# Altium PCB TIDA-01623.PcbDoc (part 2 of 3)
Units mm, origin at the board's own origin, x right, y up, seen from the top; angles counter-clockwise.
Board outline 77.73 x 42 mm, 4 copper layers (Top Layer, Signal Layer 1, Signal Layer 2, Bottom Layer), stack 0.651 mm thick; 213 components, 127 nets, 575 pads, 342 vias.
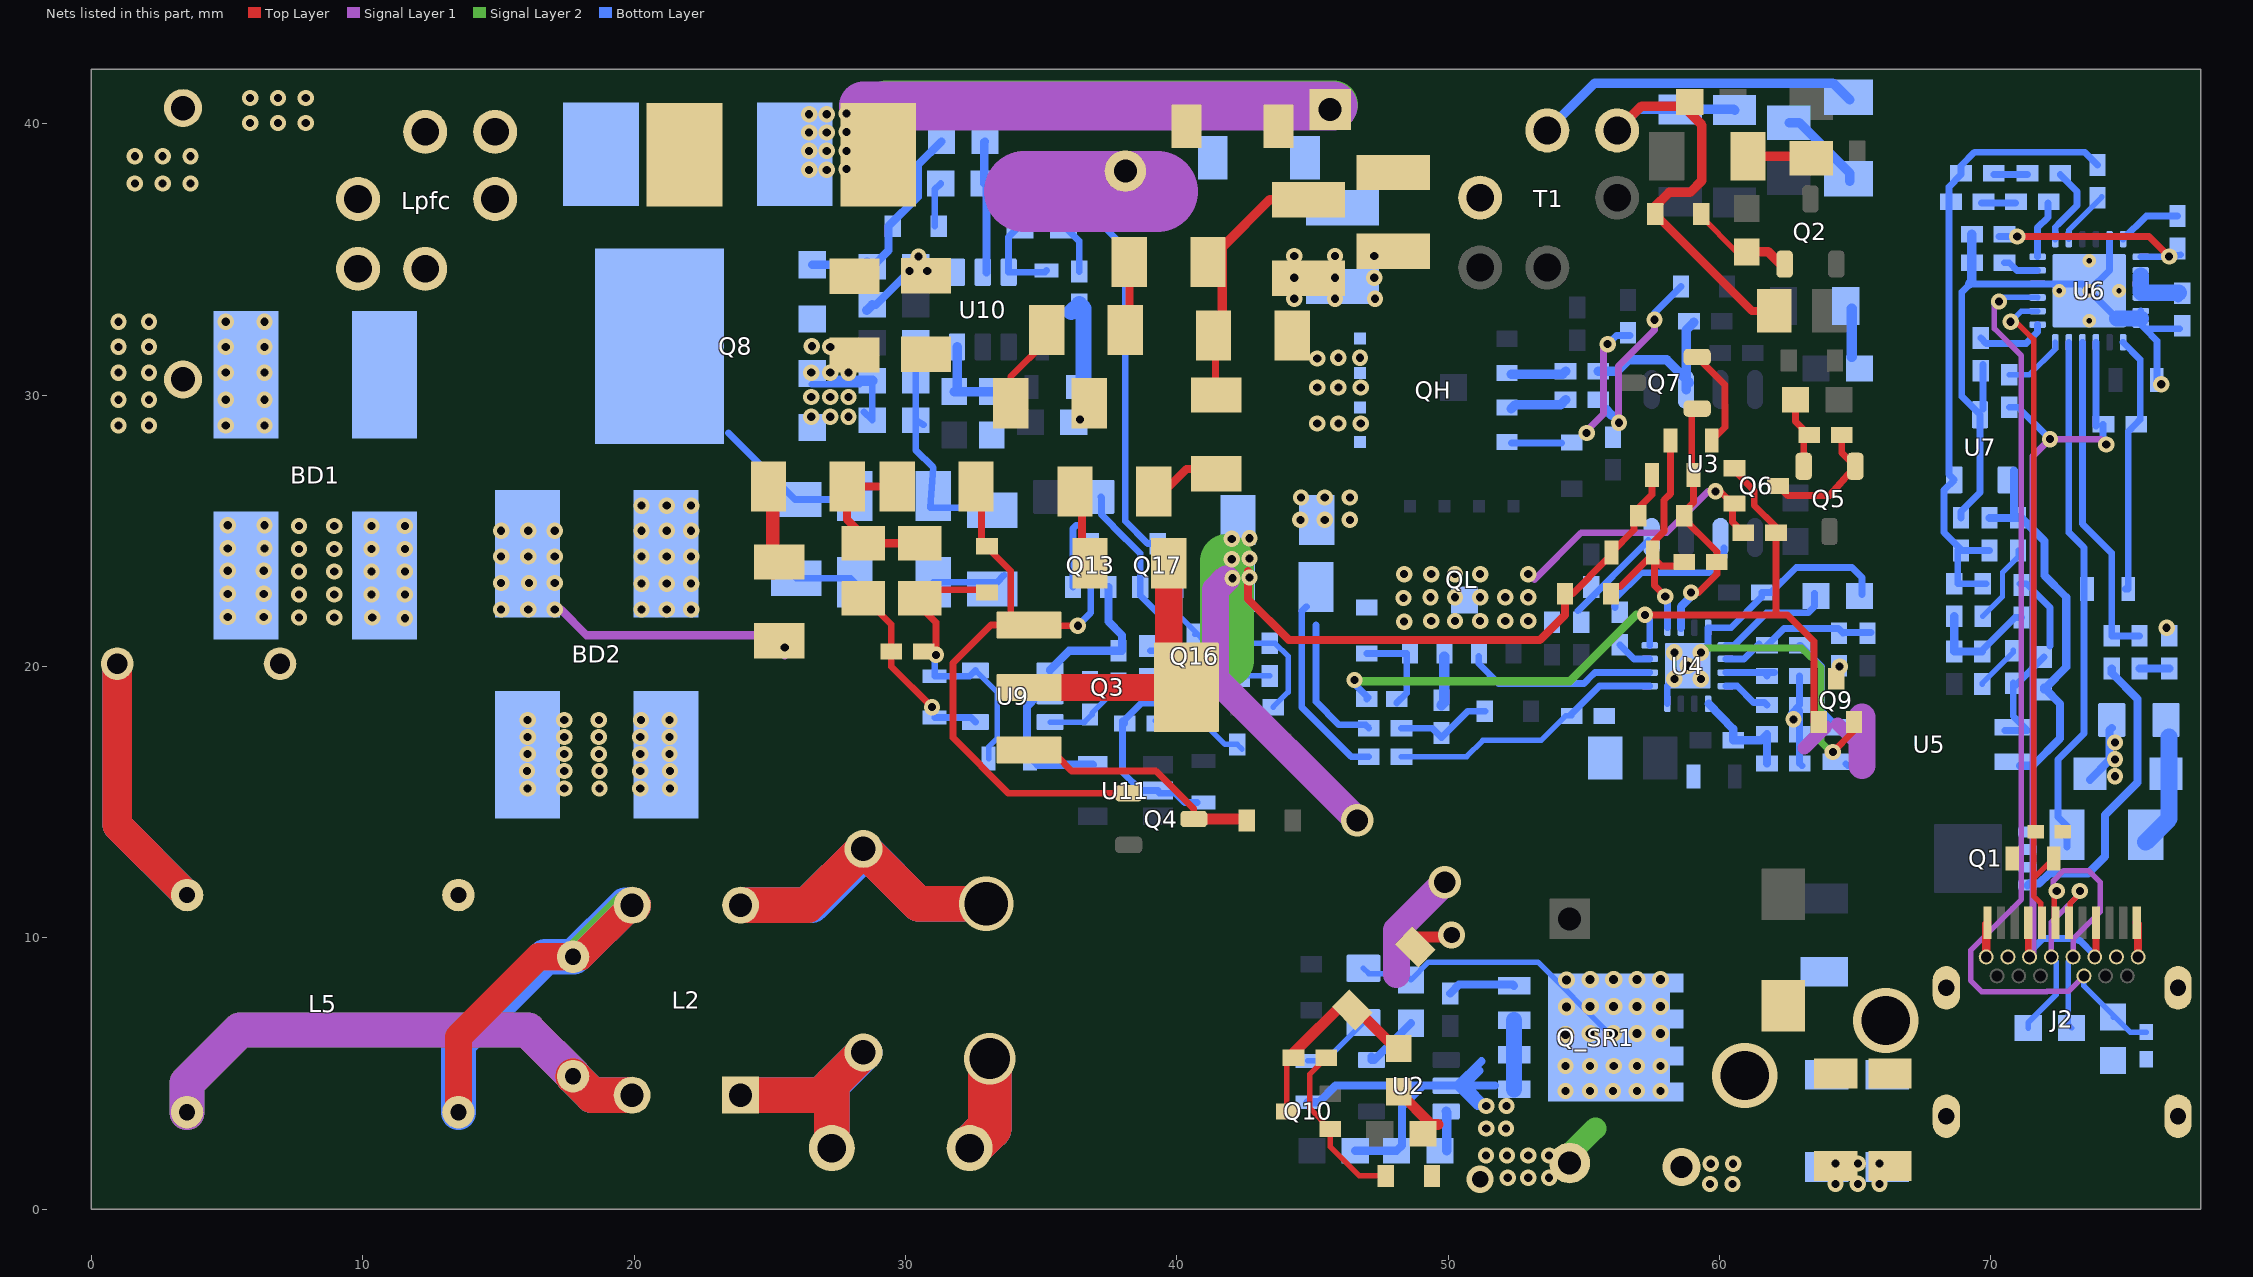
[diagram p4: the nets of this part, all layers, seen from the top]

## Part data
BD1 BD2: "Diode, P-N-Bridge, 600 V, 4 A, Z4-D"
C1: "CAP, CERM, 220 pF, 250 V, +/- 10%, X7R, 0603"
C2: "CAP, CERM, 0.33 µF, 10 V, +/- 10%, X5R, 0402"
C3: "CAP, Aluminum Polymer, 680 µF, 20 V, +/- 20%, 0.012 ohm, TH"
C4 C5 C6 C7: "CAP, CERM, 33 µF, 25 V, +/- 20%, X5R, 1206"
C8 C35: "CAP, CERM, 0.01 µF, 50 V, +/- 5%, X7R, 0402"
C10: "CAP, CERM, 6.8 µF, 25 V, +/- 10%, X5R, 0805"
C11 C12 C13: library part GRM31CR72E104KW03L, "CAP, CERM, 0.1 µF, 450 V, +/- 10%, X7T, 1206"
C14 C17 C19 C25 C52: "CAP, CERM, 0.022 µF, 50 V, +/- 10%, X7R, 0402"
C15 C20: "CAP, CERM, 0.1 µF, 50 V, +/- 10%, X7R, 0402"
C16 C51: "CAP, CERM, 0.01 µF, 50 V, +/- 10%, C0G/NP0, 0402"
C18: "CAP, CERM, 0.22 µF, 25 V, +/- 20%, X5R, 0402"
C21 C37: "CAP, CERM, 0.1 µF, 50 V, +/- 10%, X7R, 0603"
C22: "CAP, CERM, 22 µF, 35 V, +/- 20%, JB, 0805"
C23 C28: library part GRM31CR71H475KA12L, "CAP, CERM, 4.7 µF, 50 V, +/- 10%, X7R, 1206"
C26: "CAP, CERM, 22 pF, 50 V, +/- 5%, C0G/NP0, 0402"
C27 C70: "CAP, CERM, 2.2 µF, 50 V, +/- 10%, X5R, 0603"
C29 C31 C41 C61 C76 C78: "CAP, CERM, 1 µF, 50 V, +/- 10%, X7R, 0603"
C30: "CAP, CERM, 4700 pF, 50 V, +/- 10%, X7R, 0402"
C32 C33: "CAP, CERM, 560 pF, 50 V, +/- 10%, X7R, 0603"
C34: "CAP, CERM, 100 pF, 50 V, +/- 5%, C0G/NP0, 0402"
C36: "CAP, CERM, 3.3 pF, 50 V, +/- 5%, C0G/NP0, 0402"
C38: "CAP, CERM, 22 pF, 50 V, +/- 5%, C0G/NP0, 0603"
C39 C63: "CAP, CERM, 2200 pF, 50 V, +/- 5%, C0G/NP0, 0603"
C42 C43 C44: library part C3225X7R2A334K200AA, "CAP, CERM, 0.33 µF, 250 V, +/- 10%, X7T, 1210"
C47 C54: "CAP, CERM, 220 pF, 50 V, +/- 5%, C0G/NP0, 0402"
C50: "CAP, CERM, 4.7 µF, 50 V, +/- 10%, X6S, 0805"
C57: "CAP, CERM, 3900 pF, 100 V,+/- 10%, X7R, 0603"
C59: "CAP, CERM, 0.033 µF, 50 V, +/- 10%, X7R, 0603"
C60: "CAP, CERM, 1 µF, 25 V, +/- 10%, X7R, 0603"
C62 C77: "CAP, CERM, 220 pF, 50 V, +/- 5%, C0G/NP0, 0603"
C65: "CAP, CERM, 10 pF, 1000 V, +/- 5%, C0G/NP0, 1206"
C66: "CAP, CERM, 1 µF, 25 V, +/- 10%, X7R, 0805"
C75: "CAP, CERM, 0.1 µF, 250 V, +/- 10%, X7T, 0805"
C79: "CAP, CERM, 0.033 µF, 25 V, +/- 10%, X7R, 0402"
C#1: "CAP, Film, 0.47 µF, 450 V, +/- 10%, TH"
Cblk: library part 450BXW68MEFC12.5X45, "CAP, AL, 68 µF, 420 V, +/- 20%, TH"
CX1: library part 890324022017, "WCAP-FTX2 Film Capacitors, 10x6x12mm, 275V AC, 68 nF"
CX2: library part 890324024002, "WCAP-FTX2 Film Capacitors, 15x7x12.5mm, 275V AC, 220 nF"
D1: "Diode, Switching, 800 V, 3 A, SMC"
D2: "Diode, Ultrafast, 600 V, 3 A, SMC"
D3: library part PMEG10010ELRX, "Diode, Schottky, 40 V, 3 A, AEC-Q101, SOD-123W"
D4 D10: library part CZRU52C5V6, "Diode, Zener, 6.2 V, 150 mW, SOD-523F"
D6 D15: library part CZRU52C5V6, "Diode, Zener, 16 V, 150 mW, SOD-523F"
D7: "Diode, Superfast Rectifier, 600 V, 0.2A"
D8 D9: library part CZRU52C5V6, "Diode, Zener, 2 V, 150 mW, SOD-523F"
D11: "Diode, Schottky, 40 V, 0.03 A, SOD-523"
D13: library part CZRU52C5V6, "Diode, Zener, 10V, 150 mW, SOD-523F"
D14 D19 DA3: "Diode, Schottky, 50 V, 0.2 A, SOD-523F"
D16: library part CDBU0245, "Diode, Schottky, 50 V, 0.2 A, SOD-523F"
D17: "Diode, Ultrafast, 200 V, 1 A, SOD-123"
D25: library part CZRU52C5V6, "Diode, Zener, 11 V, 150 mW, SOD-523F"
D30: "Diode, Schottky, 30 V, 0.2 A, SOD-523"
DA1 DA2: "Diode, Superfast Rectifier, 600 V, 1 A, 3.5x1.6mm"
DE1 DE2: library part TPD1E0B04DPYR, "1-Channel ESD Protection Diode for USB Type-C and Antenna Protection, DPY0002A (X1SON-2)"
Dhvg1: library part CZRU52C5V6, "Diode, Zener, 24 V, 150 mW, SOD-523F"
Dz1: library part CZRU52C5V6, "Diode, Zener, 20 V, 150 mW, SOD-523F"
F1: library part 39213150000, "Fuse, 5 A, 250VAC/VDC, TH"
J2: "Connector, Receptacle, USB Type C, R/A"
L1: "WE-FI Leaded Toroidal Line Choke, L = 140µH"
L2 L5: library part 744823210, "Coupled inductor, 5.5mH+/-32%, 2.5 A, 0.040 ohm"
L3: library part 744316022, "FIXED IND 1UH 11.5A 4.75 MOHM"
L4: library part 744042330, "Inductor, Multilayer, Ferrite, 0.68 µH, 0.19 A, 0.67  ohm, 1206"
Logo2: library part Pb-Free
LOGO5 LOGO6 LOGO7 LOGO8: library part IEC_HighVoltage, "IEC 61010-1 High Voltage Warning"
LOGO9: library part IEC_HotSurface, "IEC 61010-1 Hot Surface Warning"
Lpfc: library part "RM4, 070-5754", "Transformer 6-Terminal , THT, Vertical, RM Style Bobbins, RM4"
Q1: library part CSD17578Q3A, "MOSFET, N-CH, 30 V, 27 A, DNH0008A (VSONP-8)"
Q2: library part PMV213SN,215, "MOSFET, N-CH, 100 V, 1.9 A, SOT-23"
Q3: library part STN3N40K3, "MOSFET, N-CH, 600 V, 0.3 A, SOT-223"
Q4: "MOSFET, N-CH, 60 V, 115 A, SOT-23"
Q5: library part DMP3099L-7, "'MOSFET P-CH 50V 0.18A SOT23"
Q6 Q9 Q13 Q16 Q17: "MOSFET, N-CH, 60 V, 0.31 A, SOT-323"
Q7: "MOSFET, N-CH, 600 V, 0.021 A, AEC-Q101, SOT-23"
Q8: library part IPL65R099C7, "CoolMos C7 700V Power Transistor"
Q10: "MOSFET, N-CH, 100 V, 0.17 A, SOT-323"
Q_SR1: "MOSFET, N-CH, 150 V, 87 A, PG-TDSON-8"
QH QL: library part CMP-0077886-1, "650V AllGaN Power IC with iDrive, PQFN-8"
R1: "RES, 0.005, 1%, 0.25 W, 1206"
R2: "RES, 22, 5%, 0.125 W, 0805"
R3: "RES, 1.00 k, 1%, 0.063 W, 0402"
R4: "RES, 2.21 M, 1%, 0.25 W, 1206"
R5 R25 R81 R87 R88: "RES, 10.0, 1%, 0.063 W, 0402"
R6 RG1: "RES, 10.0, 1%, 0.1 W, 0603"
R8 R31 R84 R95 R99: "RES, 100 k, 1%, 0.063 W, 0402"
R10 R27: "RES, 100, 1%, 0.1 W, 0603"
R11: "RES, 5.11, 1%, 0.1 W, 0603"
R12 R82: "RES, 100, 1%, 0.063 W, 0402"
R13 R19 R85 R96: "RES, 0, 5%, 0.063 W, 0402"
R14: "RES, 825, 1%, 0.063 W, 0402"
R15: "RES, 2.00 k, 1%, 0.063 W, 0402"
R16: "RES, 90.9 k, 1%, 0.063 W, 0402"
R17 R18 R75 R76: "RES, 0.22, 1%, 0.25 W, 1206"
R20: "RES, 61.9 k, 1%, 0.063 W, 0402"
R21: "RES, 75.0 k, 1%, 0.063 W, 0402"
R22 R29: "RES, 10.0 k, 1%, 0.063 W, 0402"
R23: "RES, 432 k, 1%, 0.063 W, 0402"
R24: "RES, 49.9 k, 1%, 0.063 W, 0402"
R26: library part CRCW0603150KFKEA, "RES, 150 k, 1%, 0.1 W, 0603"
R28: "RES, 562, 1%, 0.063 W, 0402"
R30 R37 R41: "RES, 150 k, 1%, 0.063 W, 0402"
R32 R86: "RES, 30.1 k, 1%, 0.063 W, 0402"
R33 Rb2: "RES, 56.2 k, 1%, 0.063 W, 0402"
R34: "RES, 15.0 k, 1%, 0.063 W, 0402"
R35: "RES, 121, 1%, 0.1 W, 0603"
R36: "RES, 1.00 M, 1%, 0.063 W, 0402"
R38: "RES, 274 k, 1%, 0.063 W, 0402"
R43: "RES, 24.9, 1%, 0.1 W, 0603"
R44 R45: "RES, 1.00, 1%, 0.125 W, 0805"
R46 R47 R48 R60 R61 R62 R71 R72 R73: "RES, 3.24 M, 1%, 0.25 W, 1206"
R49 R50 R51: "RES, 1.00 k, 1%, 0.25 W, 1206"
R63: "RES, 274 k, 1%, 0.1 W, 0603"
R65: "RES, 2.00, 1%, 0.1 W, 0603"
R66: "RES, 64.9 k, 1%, 0.1 W, 0603"
R68: "RES, 182 k, 1%, 0.063 W, 0402"
R74: "RES, 24.3 k, 0.5%, 0.1 W, 0603"
R78: "RES, 750, 1%, 0.1 W, 0603"
R80: "RES, 47.5 k, 1%, 0.063 W, 0402"
R83: "RES, 178 k, 1%, 0.063 W, 0402"
R97: "RES, 39.2 k, 1%, 0.063 W, 0402"
R98: "RES, 3.16 M, 1%, 0.125 W, 0805"
Rb1: "RES, 332 k, 1%, 0.063 W, 0402"
RG2: "RES, 1.00, 1%, 0.1 W, 0603"
RG3: "RES, 82.5 k, 1%, 0.1 W, 0603"
RT1: "Thermistor NTC, 47.0k ohm, 1%, 0603"
Rvs1: library part CRCW060375K0FKEA, "RES, 75.0 k, 1%, 0.1 W, 0603"
Rvs2: "RES, 12.4 k, 1%, 0.063 W, 0402"
T1: library part Transformer, "Transformer, 120 uH, SMT"
U2: "UCC24612-1DBV, DBV0005A (SOT-23-5)"
U3: library part ISO7310CDR, "Robust EMC, Low Power, Single Channel Digital Isolator, D0008A (SOIC-8)"
U4: "Active-Clamp Flyback Controller, RTE0016C (WQFN-16)"
U5: library part HMHA2801A, "Optocoupler, 3.75 kV, 80-160% CTR, SMT"
U6: "USB Type-C and USB PD Source Controller, RGE0024H (VQFN-24)"
U7: library part TL431ACDBZR, "Adjustable Precision Shunt Regulator, 34 ppm / degC, 100 mA, 0 to 70 degC, 3-pin SOT-23 (DBZ), Green (RoHS & no Sb/Br)"
U9: "Tiny CMOS Operational Amplifier with Rail-to-Rail Input and Output, DBV0005A"
U10: "6-Pin Single-Phase Transition-Mode PFC Controller, DBV0006A (SOT-23-6)"
U11: "Micropower 100 mA Ultra Low-Dropout Regulator, 5-pin SOT-23"

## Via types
v1: diameter 0.6, hole 0.3, Top Layer to Bottom Layer, 299 vias
v2: diameter 0.635, hole 0.33, Top Layer to Bottom Layer, 15 vias
v3: diameter 0.5, hole 0.2, Top Layer to Bottom Layer, 12 vias
v4: diameter 0.61, hole 0.305, Top Layer to Bottom Layer, 5 vias
v5: diameter 1, hole 0.6, Top Layer to Bottom Layer, 2 vias
v6: diameter 2.4, hole 1.8, Top Layer to Bottom Layer, 2 vias
v7: diameter 1.2, hole 0.8, Top Layer to Bottom Layer, 2 vias
v8: diameter 1.4, hole 0.8, Top Layer to Bottom Layer, 2 vias
v9: diameter 2, hole 1.6, Top Layer to Bottom Layer, 1 vias
v10: diameter 1.9, hole 1.5, Top Layer to Bottom Layer, 1 vias
v11: diameter 0.6/0.6/0.6/0.6 (per signal layer), hole 0.3, Top Layer to Bottom Layer, 1 vias

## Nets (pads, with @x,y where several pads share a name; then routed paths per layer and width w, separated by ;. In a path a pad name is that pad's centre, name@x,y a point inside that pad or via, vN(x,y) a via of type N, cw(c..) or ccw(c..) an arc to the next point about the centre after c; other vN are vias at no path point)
5V_LDO: C76.2 R84.2 U9.2 U11.5 | length 7.1
  Bottom Layer w0.3: R84.2@36.875,19.425 36.375,19.425 35.85,18.9 U9.2@35.325,18.9 34.85,18.9 34.475,18.525 34.475,16.775 34.875,16.375 U11.5@36.9,16.375
390V_BUS: C11.2 C12.2 C13.2 C42.2 C43.2 C44.2 Cblk.1 D1.1 D2.1 R4.2 R49.1 R60.2 T1.6 | length 43.4
  Top Layer w0.25: R49.1@41.425,30.175 41.425,32.1 R4.2@41.425,32.375
  Top Layer w0.35: R4.2@41.425,32.1 41.675,32.35 41.675,35.45 43.425,37.2 C44.2@44.85,37.2
  Signal Layer 1 w1.8: 28.45,40.65 Cblk.1@45.75,40.65
  Signal Layer 2 w1.8: 29.3,40.7 Cblk.1@45.775,40.7
  Bottom Layer w0.35: T1.6@51.101,37.201 T1.6@51.15,37.25
  other v1: 26.45,38.3 27.1,38.3 27.825,38.325 26.45,39 27.1,39 27.825,39 26.45,39.675 27.1,39.675 27.825,39.7 26.45,40.35 27.1,40.35 27.825,40.375
AC_IN: C77.1 R83.1 R98.1 U9.4 | length 6.5
  Top Layer w0.25: R98.1@28.725,22.509 28.725,22.3 29.475,21.55 R83.1@29.475,20.55 29.475,20 v1(30.975,18.5)
  Bottom Layer w0.25: C77.1@31.075,18.113 32.412,18.113 U9.4@32.575,17.95
AC_R: BD1.1 BD2.1 C#1.1 D1.2 Lpfc.4 Lpfc.5 Lpfc.6 R46.2 | length 9.2
  Signal Layer 1 w0.3: v1(17.075,22.1) 17.3,22.1 18.25,21.15 24.8,21.15 25.55,20.4
  other v1: 25.55,20.7 15.1,22.1 16.1,22.1 15.1,23.075 16.125,23.075 17.075,23.075 15.1,24.05 16.1,24.05 17.075,24.05 15.1,25 16.1,25 17.075,25 1.6,37.8 2.625,37.8 3.65,37.8 1.6,38.8 2.625,38.8 3.65,38.8 5.85,40.025 6.875,40.025 7.9,40.025 5.85,40.95 6.875,40.95 7.9,40.95
B/O: D15.1 Q3.1 Q4.1 Q13.3 R48.1 | length 23.5
  Top Layer w0.25: R48.1@32.6,26.625 32.8,26.425 32.8,24.425 32.975,24.425 33.875,23.525 33.875,21.525 33.15,21.525 31.75,20.125 31.75,17.375 33.8,15.325 Q4.1@38.225,15.325 ; Q3.1@34.55,21.525 34.575,21.5 v1(36.35,21.5)
  Bottom Layer w0.25: v1(36.35,21.5) 36.825,21.975 Q13.3@36.825,24.525
BUR: C47.1 Rb1.1 Rb2.2 U4.13 | length 4.1
  Bottom Layer w0.305: U4.13@59.6,18.625 60.5,17.7 Rb1.1@60.5,17.275 61.525,17.275 C47.1@61.75,17.5 Rb2.2@61.75,16.425
CC1: C32.1 DE1.2 J2.A5 U6.2 | length 24.9
  Top Layer w0.203: v1(70.725,32.7) 70.925,32.7 71.573,32.052 71.573,12.186 ; J2.A5@71.875,10.555 71.827,10.603 71.827,11.28 71.573,11.533 71.573,12.186 ; C32.1@72.312,12.925 71.573,12.186
  Bottom Layer w0.203: v1(70.725,32.7) 71.12,33.095 U6.2@71.72,33.095
CC2: C33.2 DE2.2 J2.B5 U6.3 | length 35.9
  Signal Layer 1 w0.203: v1@70.304,33.627 70.125,33.448 70.125,33.151 70.123,33.149 70.123,32.949 70.123,32.451 71.125,31.449 71.125,11.41 69.248,9.534 69.248,8.427 69.657,8.018 72.064,8.018 72.07,8.025 72.855,8.025 J2.B5@73.425,8.595
  Bottom Layer w0.203: v1@70.304,33.595 70.544,33.595 70.546,33.597 71.72,33.597 U6.3@71.72,33.595 ; J2.B5@73.425,8.595 73.425,8.225 75.125,6.525 DE2.2@75.725,6.525 ; C33.2@74.5,7.075 C33.2@74.55,7.075
  other v1: 70.3,33.45
COMP: C59.1 C60.1 Q17.3 U10.6 | length 19.8
  Bottom Layer w0.25: C59.1@35.2,34.587 35.138,34.525 U10.6@33.8,34.525 33.8,35.825 C60.1@34.225,36.25 34.39,36.25 35.19,37.05 36.46,37.05 38.1,35.41 38.1,25.35 38.925,24.525 Q17.3@39.3,24.525
CS: C26.2 R14.1 U4.1 | length 10.2
  Bottom Layer w0.2: R14.1@48.275,16.675 50.675,16.675 51.275,17.275 53.425,17.275 54.325,18.175 C26.2@54.55,18.175
  Bottom Layer w0.254: C26.2@54.512,18.212 55.575,19.275 U4.1@57.425,19.275
CTL: C35.2 C36.1 R13.1 R15.1 R21.2 R30.1 R41.2 U7.2 | length 23.6
  Bottom Layer w0.25: R41.2@68.775,24.275 68.775,23.05 C35.2@69.825,23.05 ; C36.1@69.95,24.275 R41.2@68.9,24.275 68.9,24.315 68.275,24.94 68.275,26.5 U7.2@68.65,26.875 68.625,26.9 68.45,27.075 68.45,37.675 68.9,38.125 68.9,38.45 69.4,38.95 73.45,38.95 R21.2@73.925,38.475
CTL1: R20.2 U6.6 | length 2.1
  Bottom Layer w0.25: U6.6@71.72,35.095 71.72,36.17 72.1,36.55 R20.2@72.1,37.075
CTL2: R16.2 U6.7 | length 3
  Bottom Layer w0.25: U6.7@72.37,35.745 72.37,36.184 72.55,36.364 72.55,36.365 73.175,36.99 73.175,37.5 R16.2@72.55,38.125
CTL3: R21.1 U6.8 | length 2.1
  Bottom Layer w0.2: U6.8@72.87,35.745 72.87,36.083 R21.1@74.087,37.3
DAUX2_2: DA2.2 T1.1 | length 12.2
  Bottom Layer w0.35: T1.1@53.625,39.725 T1.1@53.65,39.75 55.398,41.498 64.177,41.498 DA2.2@64.8,40.875
DN: J2.A7 J2.B7 R27.2 | length 7.4
  Top Layer w0.203: J2.A7@72.875,10.555 72.923,10.603 72.923,11.28 73.368,11.725 v1@73.375,11.725
  Signal Layer 1 w0.203: J2.B7@72.225,9.295 72.225,10.575 v1@73.375,11.725
  Bottom Layer w0.203: R27.2@71.375,6.675 71.375,6.875 72.4,7.9 72.4,8.178 72.402,8.18 72.402,9.118 J2.B7@72.225,9.295
  other v1: 73.275,11.725
DP: J2.A6 J2.B6 R27.1 | length 9.5
  Top Layer w0.2: v11@72.3,11.725 72.325,11.7 72.325,10.605 J2.A6@72.375,10.555
  Signal Layer 1 w0.2: v11@72.3,11.725 72.3,12.1 72.675,12.475 73.6,12.475 74.025,12.05 74.025,10.95 73.025,9.95 J2.B6@73.025,9.295
  Bottom Layer w0.2: R27.1@72.975,6.675 72.85,6.8 72.85,9.12 J2.B6@73.025,9.295
  other v11: 72.425,11.725
DRAIN: C65.1 D2.2 Lpfc.1 Lpfc.2 Lpfc.3 Q8.5 R71.2 | length 6.1
  Bottom Layer w0.25: 23.475,28.6 25.925,26.15 R71.2@25.975,26.15 28,26.15 C65.1@28.1,26.25 ; C65.1@28.1,26.5 C65.1@28.1,26.25 ; C65.1@28.125,26.275 C65.1@28.1,26.25 ; C65.1@28.25,26.375 C65.1@28.35,26.475
DRV: RG1.1 RG2.1 U10.5 | length 4.8
  Bottom Layer w0.3: RG2.1@32.9,37.8 32.9,39.325 RG1.1@32.925,39.35 ; U10.5@32.979,34.521 RG2.1@32.979,37.8
DVDD: C18.1 R19.2 U6.13 | length 8.1
  Top Layer w0.254: v1(70.97,35.845) 75.824,35.845 v1(76.567,35.102)
  Bottom Layer w0.254: C18.1@70.3,35.85 v1(70.97,35.845) ; U6.13@75.52,35.095 76.567,35.095 R19.2@76.995,35.17
F: Q_SR1.5 Q_SR1.6 Q_SR1.7 Q_SR1.8 Q_SR1.9 R2.1 R10.2 | length 10.7
  Bottom Layer w0.2: R2.1@46.875,8.875 47.075,8.675 48.4,8.675 R10.2@48.625,8.45 49.275,9.1 53.3,9.1 55.925,6.475 Q_SR1.9@55.925,6.325
  other v1: 54.325,4.35 55.225,4.35 56.075,4.35 56.95,4.35 57.825,4.35 54.325,5.275 55.225,5.275 56.1,5.275 56.95,5.275 57.825,5.275
  other v2: 54.327,6.436 55.225,6.475 56.089,6.475 56.952,6.475 57.816,6.475 54.36,7.457 55.233,7.47 56.096,7.47 56.96,7.47 57.823,7.47 54.36,8.445 55.233,8.459 56.096,8.459 56.96,8.459 57.823,8.459
  other v6: 60.925,4.925
FB: C54.2 R23.2 R32.1 U4.10 | length 5.7
  Bottom Layer w0.25: U4.10@60.225,20.275 60.9,20.275 R32.1@61.45,20.825 ; R32.1@61.7,20.725 R32.1@61.75,20.775 62.375,21.4 64.375,21.4 64.55,21.225 64.575,21.25 C54.2@65.575,21.25
GATE: D14.2 Q8.1 RG1.2 RG3.2 | length 8.1
  Bottom Layer w0.3: Q8.1@26.565,34.8 RG3.2@28.7,34.8 ; RG3.2@28.575,34.925 RG3.2@28.7,34.8 ; RG1.2@31.325,39.35 30.45,38.475 30.45,37.3 29.375,36.225 29.375,35.325 RG3.2@28.775,34.725 RG3.2@28.7,34.8
GDNG: R3.2 R5.1 U6.22 | length 12.3
  Bottom Layer w0.25: U6.22@73.37,31.945 73.37,25.255 74.45,24.175 R5.1@74.45,21.125 R3.2@75.475,21.125
GDNS: Q1.1 Q1.2 Q1.3 R1.1 R43.2 U6.23 | length 19.4
  Bottom Layer w0.25: R1.1@72.8,13.35 72.8,14.125 72.475,14.45 72.475,16.575 73.425,17.525 73.425,24.375 72.87,24.93 U6.23@72.87,31.945
HIGH_VOUT: D25.2 Q16.1 R22.1 | length 5.7
  Bottom Layer w0.2: R22.1@39.2,18 R22.1@39.275,18 ; R22.1@39.275,17.9 40.175,17.9 ; Q16.1@41.3,19.575 41.3,19.025 40.175,17.9 ; D25.2@42.4,16.95 D25.2@42.225,17.125 41.775,17.125 41,17.9 40.175,17.9
HVG: C39.2 Dhvg1.1 Q7.1 R36.2 U4.6 | length 9.7
  Top Layer w0.25: Dhvg1.1@58.55,25.55 59.037,26.037 59.037,26.262 C39.2@59.037,27.05 58.975,27.112 58.975,29.3 Q7.1@59.175,29.5 ; Dhvg1.1@58.563,25.563 59.9,24.225 R36.2@59.9,23.85 59.9,23.4 59.225,22.725 v1(58.95,22.725)
  Bottom Layer w0.305: U4.6@58.575,21.425 58.575,22.2 58.95,22.575 v1(58.95,22.725)
INH: C34.2 R88.1 U3.6 | length 6.5
  Bottom Layer w0.35: R88.1@55.525,30.875 56.225,30.875 56.65,31.3 58.05,31.3 U3.6@58.765,30.585 ; U3.6@58.765,30.2 U3.6@58.765,30.585 ; U3.6@58.89,30.46 U3.6@58.765,30.585 ; C34.2@59.05,32.675 58.765,32.39 U3.6@58.765,30.585
ISNS: C2.2 R43.1 U6.19 | length 9.6
  Bottom Layer w0.25: U6.19@74.87,31.945 75.5,31.315 75.5,29.1 75.325,28.925 75.062,28.662 R43.1@75.062,22.85 R43.1@74.95,22.85
L-LINE: F1.2 | length 14.4
  Top Layer w1.6: F1.2@32.365,2.25 33.1,2.985 v10(33.1,5.55)
  Signal Layer 1 w1.6: F1.2@32.365,2.25 33.1,2.985 v10(33.1,5.55)
  Signal Layer 2 w1.6: F1.2@32.365,2.25 33.1,2.985 v10(33.1,5.55)
  Bottom Layer w1.6: F1.2@32.365,2.25 33.1,2.985 v10(33.1,5.55)
N-LINE: CX1.1 L2.4 | length 42.9
  Top Layer w1.3: L2.4@23.925,11.2 26.375,11.2 CX1.1@28.45,13.275 30.475,11.25 v9(32.975,11.25)
  Signal Layer 1 w1.3: L2.4@23.925,11.2 26.375,11.2 CX1.1@28.45,13.275 30.475,11.25 v9(32.975,11.25)
  Signal Layer 2 w1.3: L2.4@23.925,11.2 26.375,11.2 CX1.1@28.45,13.275 30.475,11.25 v9(32.975,11.25)
  Bottom Layer w1.3: L2.4@23.975,11.2 26.55,11.2 28.537,13.187 30.475,11.25 v9(32.975,11.25)
NetBD1_2: BD1.2 BD1.3 L1.2
  other v1: 11.55,21.775 7.65,21.8 8.95,21.8 10.35,21.8 5.025,21.825 6.35,21.825 7.65,22.65 8.95,22.65 10.325,22.65 11.55,22.65 5.025,22.675 6.35,22.675 7.65,23.5 8.95,23.5 10.325,23.5 11.55,23.5 5.025,23.525 6.35,23.525 7.65,24.325 8.95,24.325 10.325,24.325 11.55,24.325 5.025,24.35 6.375,24.35 7.65,25.175 8.95,25.175 10.325,25.175 11.55,25.175 5.025,25.2 6.375,25.2
NetBD2_2: BD2.2 BD2.3 L5.3
  other v1: 16.075,15.5 17.425,15.5 18.725,15.5 20.225,15.5 21.325,15.5 16.05,16.15 17.425,16.15 18.725,16.15 20.225,16.15 21.325,16.15 16.075,16.775 17.425,16.775 18.7,16.775 20.225,16.775 21.3,16.775 16.075,17.4 17.425,17.4 18.7,17.4 20.225,17.4 21.3,17.4 16.075,18.025 17.425,18.025 18.7,18.025 20.25,18.025 21.3,18.025
NetC1_2: C1.2 R2.2 | length 2.6
  Bottom Layer w0.2: C1.2@44.825,5.462 45.462,5.462 R2.2@46.875,6.875
NetC8_1: C8.1 R3.1 | length 1.1
  Bottom Layer w0.3: R3.1@75.475,19.925 C8.1@76.575,19.925
NetC16_1: C16.1 D8.1 R81.2 | length 6.3
  Signal Layer 1 w0.254: v1(56.294,28.979) 56.275,28.998 56.275,31.074 57.6,32.399 v1(57.6,32.775)
  Bottom Layer w0.254: v1(57.6,32.775) 57.6,33.025 D8.1@58.575,34
  Bottom Layer w0.35: 55.773,29.5 56.025,29.249
NetC20_1: C20.1 U6.1 | length 2.6
  Bottom Layer w0.254: C20.1@69.625,32.1 69.825,31.9 71.3,31.9 71.72,32.32 U6.1@71.72,32.595
NetC29_2: C29.2 D17.1 Q10.3 R24.1 | length 7.2
  Top Layer w0.2: Q10.3@44.05,3.6 44.05,5.325 R24.1@44.3,5.575
  Top Layer w0.4: R24.1@44.3,5.575 44.3,5.75 46.267,7.717 47.809,6.175 C29.2@47.825,6.175
NetC30_1: C30.1 R28.1 | length 1.7
  Bottom Layer w0.2: R28.1@69.675,19.35 69.675,19.374 70.825,20.524 C30.1@70.825,20.6
NetC30_2: C30.2 R29.1 R34.2 U5.1 | length 7.2
  Bottom Layer w0.25: U5.1@70.51,17.635 71.35,17.635 70.825,18.16 C30.2@70.825,19.4 ; C30.2@70.9,19.3 R34.2@71.95,20.35 ; R29.1@71.075,23.05 71.3,23.05 72.175,22.175 R34.2@72.175,20.75
NetC35_1: C35.1 R33.2 | length 3
  Bottom Layer w0.2: C35.1@69.7,21.85 70.425,22.575 70.425,23.465 71,24.04 R33.2@71,24.275
NetC36_2: C36.2 R33.1 R34.1 U5.2 U7.1 | length 14.5
  Bottom Layer w0.3: C36.2@69.95,25.475 R33.1@71,25.475 R33.1@70.975,25.5 ; R33.1@70.85,25.5 70.85,27.225 ; R33.1@70.875,25.475 71.125,25.475 71.975,24.625 71.975,23.35 72.775,22.55 72.775,19.975 R34.1@72.025,19.225 ; U5.2@71.075,16.34 71.54,16.34 72.55,17.35 72.55,18.625 71.988,19.188 71.95,19.225 R34.1@72.025,19.225 ; R34.1@71.95,19.15 R34.1@72.025,19.225
NetC42_1: C42.1 C43.1 C44.1 QH.5 QH.6 QH.7 QH.8 R4.1
  other v1: 45.175,28.95 45.95,28.95 46.775,28.95 45.175,30.275 45.95,30.275 46.775,30.275 45.175,31.35 45.95,31.375 46.75,31.375 44.325,33.55 45.825,33.55 47.3,33.55 44.325,34.325 45.825,34.325 47.275,34.325 44.325,35.125 45.825,35.125 47.275,35.125
NetC51_1: C51.1 D9.1 R82.2 | length 3.6
  Bottom Layer w0.25: C51.1@48.275,17.725 49.4,17.725 49.75,17.375 50.725,18.35 D9.1@51.35,18.35
NetC57_1: C57.1 C65.2 R73.1 R74.2 R78.2 | length 8.7
  Bottom Layer w0.25: R78.2@30.375,31.925 C57.1@30.375,30.525 R74.2@30.375,29.075 ; R74.2@30.675,28.904 R74.2@30.375,29.075 ; R73.1@32.94,25.85 30.915,25.85 31.025,27.325 30.375,27.975 R74.2@30.375,29.075
NetC57_2: C57.2 Q8.2 Q8.3 Q8.4 R74.1 R75.2 R76.2 | length 5
  Bottom Layer w0.25: Q8.3@26.55,30.395 C57.2@28.3,30.395 ; R74.1@28.475,29.375 R74.1@28.775,29.075 C57.2@28.775,30.525
  Bottom Layer w0.4: 27.4,30.525 C57.2@28.775,30.525
  other v1: 26.525,29.2 27.225,29.2 27.9,29.2 26.525,29.925 27.225,29.925 27.9,29.925 26.525,30.825 27.225,30.825 27.9,30.825 27.225,31.775 26.55,31.8
NetC60_2: C60.2 R68.2 | length 1.9
  Bottom Layer w0.25: C60.2@35.825,36.25 36.4,35.675 R68.2@36.4,34.55
NetC75_1: C75.1 R47.1 R48.2 R98.2 | length 6.1
  Top Layer w0.3: R48.2@29.7,26.625 R47.1@27.85,26.625 27.85,25.416 28.725,24.541 30.359,24.541 C75.1@30.475,24.425
NetC79_1: C79.1 Q16.3 Q17.1 R31.2 R95.1 | length 8
  Bottom Layer w0.2: Q17.1@39.95,22.925 40.1,22.775 40.1,21.85 Q16.3@40.775,21.175 ; Q16.3@40.65,21.175 Q16.3@40.775,21.175 ; R31.2@43.55,18.5 44.1,19.05 44.1,20.375 43.625,20.85 43.475,20.85 C79.1@43.425,20.85 R95.1@42.4,20.85 42.25,21 40.95,21 Q16.3@40.775,21.175
NetCX1_2: CX1.2 F1.1 L2.1 | length 30
  Top Layer w1.3: L2.1@23.925,4.2 26.875,4.2 27.285,4.61 ; F1.1@27.285,2.25 27.285,4.61 ; CX1.2@28.45,5.775 27.285,4.61
  Signal Layer 1 w1.3: L2.1@23.925,4.2 26.875,4.2 27.285,4.61 ; F1.1@27.285,2.25 27.285,4.61 ; CX1.2@28.45,5.775 27.285,4.61
  Signal Layer 2 w1.3: L2.1@23.925,4.2 26.875,4.2 27.285,4.61 ; F1.1@27.285,2.25 27.285,4.61 ; CX1.2@28.45,5.775 27.285,4.61
  Bottom Layer w1.3: L2.1@23.975,4.2 27.05,4.2 27.285,4.435 ; F1.1@27.285,2.25 27.285,4.435 ; CX1.2@28.5,5.775 27.285,4.56 27.285,4.435
NetCX2_1: CX2.1 L2.3 L5.4 | length 28.2
  Top Layer w1: L5.4@13.525,3.575 13.525,6.35 16.475,9.3 CX2.1@17.75,9.3 18.025,9.3 L2.3@19.925,11.2
  Top Layer w1.3: L2.3@19.925,11.2 L2.3@19.975,11.2
  Signal Layer 1 w1: CX2.1@17.75,9.3 18.025,9.3 L2.3@19.925,11.2
  Signal Layer 2 w1: CX2.1@17.75,9.3 19.65,11.2 L2.3@19.925,11.2
  Bottom Layer w1.3: L5.4@13.525,3.575 13.525,6.1 16.725,9.3 CX2.1@17.75,9.3 17.775,9.3 19.675,11.2 L2.3@19.925,11.2 L2.3@19.975,11.2
NetCX2_2: CX2.2 L2.2 L5.1 | length 43.5
  Top Layer w1.3: CX2.2@17.75,4.9 18.45,4.2 L2.2@19.925,4.2
  Signal Layer 1 w1.3: L5.1@3.525,3.575 3.525,4.65 5.475,6.6 16.075,6.6 CX2.2@17.775,4.9 ; CX2.2@17.75,4.9 18.45,4.2 L2.2@19.925,4.2
  Signal Layer 2 w1.3: L5.1@3.525,3.575 3.525,4.65 5.475,6.6 16.075,6.6 CX2.2@17.775,4.9 ; CX2.2@17.75,4.9 18.45,4.2 L2.2@19.925,4.2
  Bottom Layer w1.3: CX2.2@17.75,4.9 18.45,4.2 L2.2@19.925,4.2
NetD4_1: D4.1 QH.4 R80.1 | length 6.4
  Signal Layer 1 w0.254: v1(55.1,28.6) 55.1,28.672 55.725,29.297 55.725,31.725 v1(55.875,31.875)
  Bottom Layer w0.254: QH.4@52.328,28.228 D4.1@54.172,28.228 ; v1(55.875,31.875) 56.2,32.2 R80.1@56.7,32.2
NetD6_1: D6.1 Q2.1 R26.1 | length 3.3
  Top Layer w0.2: D6.1@59.325,36.625 59.325,36.575 R26.1@60.625,35.275
  Top Layer w0.35: R26.1@61,35.275 61.8,35.275 Q2.1@62.25,34.825
NetD7_2: D7.2 R11.1 | length 1.8
  Bottom Layer w0.381: R11.1@64.875,31.4 D7.2@64.875,33.175
NetD10_1: D10.1 D11.1 QL.4 | length 3.5
  Bottom Layer w0.25: D10.1@47,20.475 48.471,20.475 48.471,19.021 D11.1@48.1,18.65
NetD13_1: D13.1 Q10.1 R24.2 | length 6.3
  Top Layer w0.2: R24.2@45.5,5.575 44.9,4.975 44.9,3.7 Q10.1@45.65,2.95 45.65,2.3 46.725,1.225 D13.1@47.7,1.225
NetD14_1: D14.1 RG2.2 | length 1.7
  Bottom Layer w0.25: D14.1@31.075,36.225 31.075,37.575 RG2.2@31.3,37.8
NetD19_1: D19.1 Q3.3 Q4.3 | length 9.3
  Top Layer w0.25: Q3.3@34.55,16.925 34.8,16.675 35.6,16.675 36.125,16.15 39.225,16.15 40.625,14.75 Q4.3@40.625,14.375
  Top Layer w0.4: Q4.3@40.625,14.375 42.525,14.375 D19.1@42.575,14.325
NetDA1_1: DA1.1 R44.2 | length 2.4
  Top Layer w0.35: DA1.1@61.15,38.8 63.484,38.8 R44.2@63.55,38.734
NetDA2_1: DA2.1 R45.2 | length 3.3
  Bottom Layer w0.35: R45.2@62.575,40.041 62.934,40.041 64.8,38.175 DA2.1@64.8,37.875
NetL1_1: L1.1 L5.2 | length 38.4
  Top Layer w1.1: L1.1@0.95,20.1 0.95,14.15 L5.2@3.525,11.575
  Signal Layer 1 w1.1: L1.1@0.95,20.1 0.95,14.15 L5.2@3.525,11.575
  Signal Layer 2 w1.1: L1.1@0.95,20.1 0.95,14.15 L5.2@3.525,11.575
  Bottom Layer w1.1: L1.1@0.95,20.1 0.95,14.15 L5.2@3.525,11.575
NetQ1_4: Q1.4 R5.2 | length 11.1
  Bottom Layer w0.3: Q1.4@71.35,11.925 71.419,11.994 71.775,11.994 72.156,12.375 73.575,12.375 74.2,13 74.2,14.525 75.4,15.725 75.4,18.805 74.45,19.755 R5.2@74.45,19.925
NetQ3_2: Q3.2 Q3.4 R51.2 | length 10.6
  Top Layer w1: Q3.2@34.55,19.225 Q3.4@40.35,19.225 39.7,19.875 R51.2@39.7,23.8
NetQ5_1: Q5.1 Q6.3 R86.1 | length 4.8
  Top Layer w0.25: Q6.3@62.15,26.65 62.5,26.3 64.062,26.3 Q5.1@65,27.375 64.5,27.875 R86.1@64.5,28.525
NetQ5_2: Q5.2 R6.2 R86.2 | length 2.7
  Top Layer w0.25: R6.2@62.8,29.825 62.8,29.025 R86.2@63.3,28.525 63.1,28.325 Q5.2@63.1,27.375
NetQ7_2: Q7.2 R35.2 | length 3.7
  Top Layer w0.25: Q7.2@59.175,31.4 60.2,30.375 60.2,28.813 R35.2@59.712,28.325
NetQ9_3: Q9.3 R23.1 | length 0.1
  Bottom Layer w0.25: R23.1@64.55,20.025 R23.1@64.6,19.975
  other v1: 64.425,20
NetQ13_1: Q13.1 R99.1 U9.1 | length 5.5
  Bottom Layer w0.3: U9.1@35.325,19.85 35.325,19.875 36.025,20.575 37.975,20.575 37.975,21.15 37.475,21.65 Q13.1@37.475,22.925
NetQ_SR1_4: Q_SR1.4 R85.1 | length 2.5
  Bottom Layer w0.3: R85.1@50.075,7.95 50.4,8.275 52.38,8.275 Q_SR1.4@52.425,8.23
NetQH_2: QH.2 R88.2 | length 2
  Bottom Layer w0.35: QH.2@52.328,30.768 54.218,30.768 R88.2@54.325,30.875
NetQH_3: QH.3 R81.1 | length 2.1
  Bottom Layer w0.35: QH.3@52.328,29.498 52.48,29.65 54.15,29.65 R81.1@54.325,29.825
NetQL_3: QL.3 R82.1 | length 1.8
  Bottom Layer w0.381: R82.1@49.75,18.575 49.854,18.679 QL.3@49.854,20.362
NetQp1_1: 
NetQp1_2: 
NetR10_1: R10.1 U2.5 | length 2.1
  Bottom Layer w0.3: U2.5@47.175,5.631 U2.5@47.175,5.5 47.275,5.5 R10.1@48.625,6.85
NetR12_1: R12.1 U6.24 | length 2.3
  Bottom Layer w0.203: R12.1@70.675,30.75 71.42,30.75 72.37,31.7 U6.24@72.37,31.945
NetR13_2: R13.2 R20.1 | length 1.2
  Bottom Layer w0.25: R13.2@69.65,37.075 R20.1@70.9,37.075
NetR15_2: R15.2 R16.1 | length 1.2
  Bottom Layer w0.25: R15.2@70.1,38.125 R16.1@71.35,38.125
NetR19_1: R19.1 U6.12 | length 2.4
  Bottom Layer w0.25: U6.12@74.87,35.745 75.725,36.6 R19.1@76.875,36.6
NetR25_1: R25.1 R28.2 R29.2 R30.2 | length 4.3
  Bottom Layer w0.25: R28.2@69.675,20.55 69.675,20.585 70.89,21.8 R29.2@71.125,21.8
  Bottom Layer w0.3: R30.2@68.65,21.85 R25.1@68.65,20.55 R28.2@69.675,20.55
NetR32_2: R32.2 U5.4 | length 4
  Bottom Layer w0.25: R32.2@62.95,20.775 62.985,20.775 63.76,20 63.76,18.365 64.515,17.61 U5.4@64.725,17.61
NetR46_1: R46.1 R47.2 | length 3.2
  Top Layer w0.5: R47.2@24.95,26.625 25.1,26.475 R46.1@25.1,23.45
NetR49_2: R49.2 R50.1 | length 2.6
  Top Layer w0.3: R50.1@39.15,26.45 39.525,26.45 40.35,27.275 R49.2@41.425,27.275
NetR50_2: R50.2 R51.1 | length 2.9
  Top Layer w0.3: R50.2@36.25,26.45 36.25,25.9 36.5,25.65 36.5,24.1 R51.1@36.8,23.8
NetR60_1: R60.1 R61.2 | length 2.6
  Top Layer w0.3: R61.2@38.1,32.4 38.25,32.55 R60.1@38.25,34.9
NetR61_1: R61.1 R62.2 | length 3.2
  Top Layer w0.25: R62.2@33.875,29.7 33.875,30.675 35.2,32 R61.1@35.2,32.4
NetR62_1: R62.1 R63.2
  other v1: 36.425,29.1
NetR71_1: R71.1 R72.2 | length 2.2
  Bottom Layer w0.25: R71.1@25.975,23.25 27.975,23.25 R72.2@28.125,23.1
NetR72_1: R72.1 R73.2 | length 2.7
  Bottom Layer w0.25: R72.1@31.025,23.1 33.375,23.1 R73.2@33.637,23.363
NetR84_1: R84.1 R97.2 R99.2 U9.3 | length 4.3
  Bottom Layer w0.2: U9.3@35.325,17.95 36.6,17.95 36.875,18.225 36.875,18.275 37.975,19.375 R97.2@39.025,19.375
NetR87_2: R87.2 U3.2 | length 5.3
  Bottom Layer w0.25: R87.2@56.15,22.175 56.15,22.5 57.1,23.45 59.6,23.45 60.16,24.01 U3.2@60.16,24.375
NetR96_1: R96.1 U6.5 | length 1.3
  Bottom Layer w0.25: R96.1@70.5,34.875 70.675,34.875 70.955,34.595 U6.5@71.72,34.595
NTC: RT1.2 U4.9 | length 4.4
  Bottom Layer w0.25: U4.9@60.225,20.775 60.525,20.775 61.725,21.975 63.261,21.975 63.5,22.214 RT1.2@63.5,22.7
PGND: BD1.4 BD2.4 C11.1 C12.1 C13.1 C22.2 C23.2 C26.1 C28.2 C37.2 C38.2 C39.1 C47.2 C50.2 C59.2 C61.2 C62.1 C63.1 C66.2 C70.2 C75.2 C76.1 C77.2 C78.1 C79.2 C#1.2 Cblk.2 D6.2 D15.2 Dhvg1.2 Dz1.2 Q9.2 Q13.2 Q16.2 Q17.2 R17.1 R18.1 R22.2 R37.2 R38.1 R66.1 R68.1 R75.1 R76.1 R83.2 R95.2 R97.1 Rb2.1 RG3.1 RT1.1 Rvs2.1 T1.2 U4.8 U4.16 U4.17@58.825,20.025 U5.3 U9.5 U10.4 U11.2 | length 131.8
  Top Layer w0.25: v1(31.125,20.425) 31.125,21.625 30.2,22.55 30.475,22.825 32.7,22.825 D15.2@32.8,22.725 ; Dz1.2@54.3,22.675 54.575,22.675 C38.2@55.838,23.938 ; C38.2@56.013,24.2 56.85,25.037 56.85,25.664 57.513,26.327 C39.1@57.513,27.05 ; v1(64.175,16.85) Q9.2@64.9,17.575
  Top Layer w0.3: v1@42.625,23.513 42.625,22.475 44.125,20.975 53.375,20.975 54.3,21.9 Dz1.2@54.3,22.675 ; D6.2@57.625,36.675 61.2,33.1 C22.2@62.009,33.1
  Top Layer w0.35: T1.2@56.2,39.725 57.125,40.65 58.65,40.65 59.35,39.95 59.35,37.9 58.925,37.475 58.15,37.475 57.625,36.95 D6.2@57.625,36.675
  Signal Layer 1 w0.5: 63.125,17 63.9,17.775 ; 64.35,17.875 64.358,17.875 65.25,16.983
  Signal Layer 1 w1: v1@41.825,23.225 41.425,22.825 41.425,19.55 v7(46.65,14.325) ; 65.25,16.35 65.25,16.983 65.25,18.125
  Signal Layer 1 w3: 34.4,37.5 39.275,37.5
  Signal Layer 2 w0.25: v4(59.313,20.513) 59.475,20.675 63.025,20.675 63.75,19.95 63.75,17.2 v1@64.175,16.775
  Signal Layer 2 w2: 34.35,38 39.225,38 ; 41.85,20.225 v1@41.85,23.875
  Bottom Layer w0.2: U9.5@32.575,19.85 33.375,19.05 33.375,17.35 33.063,17.038 C76.1@33.063,16.6 ; Q16.2@40,19.575 40.125,19.7 40.7,20.275 41.775,20.275 R95.2@42.4,19.65 C79.2@43.425,19.65
  Bottom Layer w0.25: v1(31.125,20.425) 31.075,20.375 C77.2@31.075,19.637 32.362,19.637 U9.5@32.575,19.85 ; Q13.2@36.175,22.925 36.175,25.079 36.3,25.204 ; C66.2@37.2,26.25 37.225,26.225 37.225,25.6 37.65,25.175 37.65,25.164 38.65,24.164 Q17.2@38.65,22.925 38.65,22.615 39.759,21.506 39.759,20.391 ; R22.2@38,18 38,16.1 38.675,15.425 U11.2@39.3,15.425 ; R22.2@38.075,17.9 38.075,18.025 38.7,18.65 39.6,18.65 40.125,19.175 40.125,19.675 40.025,19.575 Q16.2@40,19.575 ; R97.1@39.025,20.575 39.575,20.575 39.759,20.391 ; U11.2@39.35,15.325 39.95,15.325 40.287,14.988 C78.1@40.75,14.988 ; Q16.2@40.125,19.7 40.125,20.025 39.759,20.391 ; v7@46.65,14.1 v7(46.65,14.325) ; U4.16@58.075,18.625 58.075,19.275 v4(58.337,19.537) ; v4(59.313,20.513) 59.575,20.775 U4.8@59.575,21.425 60.425,21.425 61.55,22.55 Rvs2.1@61.55,22.725 61.9,22.725 62.825,23.65 64.875,23.65 65.25,23.275 RT1.1@65.25,22.65 ; R37.2@62.65,18.275 R37.2@62.95,18.575 R38.1@62.95,19.65 ; R37.2@62.95,18.375 C47.2@62.95,17.5 Rb2.1@62.95,16.425 Rb2.1@63.035,16.34 ; U5.3@64.653,16.412 U5.3@64.725,16.34
  Bottom Layer w0.3: C62.1@28.775,33.325 28.905,33.325 RG3.1@30.305,34.725 ; RG3.1@30.305,34.85 RG3.1@30.375,34.85 ; 41.15,22.925 R17.1@42.225,22.925
  Bottom Layer w0.35: C62.1@28.575,33.125 C62.1@28.775,33.325 ; T1.2@56.2,39.725 T1.2@56.475,39.725 ; T1.2@56.225,39.75 57,40.525 C23.2@58.55,40.525 60.525,40.525 C28.2@60.55,40.5
  Bottom Layer w0.6: R68.1@36.113,33.063 R68.1@36.4,33.35 36.562,33.188 R66.1@36.562,31.725 36.562,30.588
  other v1: 62.725,18.05 20.275,22.1 21.2,22.1 22.1,22.1 20.275,23.05 21.2,23.05 22.1,23.05 42.05,23.25 42.675,23.275 42.025,23.95 42.675,23.975 20.275,24.05 21.2,24.05 22.1,24.05 42.025,24.7 42.675,24.725 20.275,25 21.2,25 22.1,25 20.275,25.925 21.2,25.925 22.1,25.925 1,28.875 2.125,28.875 4.95,28.875 6.375,28.875 1,29.825 2.125,29.825 4.95,29.825 6.375,29.825 1,30.825 2.125,30.825 4.95,30.825 6.375,30.825 1,31.775 2.125,31.775 4.95,31.775 6.375,31.775 1,32.7 2.125,32.7 4.95,32.7 6.375,32.7 30.15,34.575 30.8,34.575 30.475,35.1
  other v4: 59.313,19.537 58.825,20.025 58.337,20.513
PGND1: C14.2 C25.2 C51.2 C52.2 D10.2 Q6.2 QL.9 R8.1 R14.2 R17.2 R18.2 U3.4 | length 25.5
  Top Layer w0.25: v1@60.025,26.45 60.475,26 60.475,25.325 R8.1@60.875,24.925
  Signal Layer 1 w0.25: 53.175,23.2 54.9,24.925 58.05,24.925 v1@59.575,26.45
  Bottom Layer w0.25: R17.2@44.775,22.2 44.6,22.025 44.6,18.5 46.425,16.675 R14.2@47.075,16.675 ; 45.125,21.525 45.125,18.7 45.978,17.847 46.953,17.847 C51.2@47.075,17.725 ; 54.775,22.05 U3.4@57.375,24.65
  other v1: 48.375,21.65 49.375,21.675 50.25,21.675 51.175,21.675 52.1,21.675 52.95,21.675 48.35,22.525 49.35,22.55 50.25,22.55 51.175,22.55 52.1,22.55 52.95,22.55 48.375,23.4 49.375,23.4 50.25,23.4 51.175,23.4 52.95,23.4 44.55,25.4 45.45,25.4 46.375,25.4 44.575,26.225 45.45,26.225 46.375,26.225 59.85,26.45
PWMH: R87.1 U4.3 | length 1.3
  Bottom Layer w0.25: R87.1@56.325,20.8 56.325,20.796 56.846,20.275 U4.3@57.425,20.275
PWML: QL.2 U4.2 | length 7
  Bottom Layer w0.25: QL.2@51.124,20.362 51.124,20.101 51.85,19.375 51.897,19.375 ; 51.897,19.374 52.89,19.374 ; 52.891,19.375 55,19.375 55.325,19.7 55.335,19.7 55.41,19.775 U4.2@57.425,19.775
RDM: R37.1 U4.12 | length 1.8
  Bottom Layer w0.25: U4.12@60.225,19.275 60.65,19.275 61.25,18.675 61.65,18.675 R37.1@61.75,18.575
REG: C27.2 U2.3 | length 1.5
  Bottom Layer w0.35: U2.3@49.925,3.6 49.95,3.575 C27.2@49.95,2.15
RTZ: R38.2 U4.11 | length 1.8
  Bottom Layer w0.25: U4.11@60.225,19.775 R38.2@62.025,19.775 ; R38.2@61.725,19.675 R38.2@61.75,19.65
RUN: D11.2 Q6.1 Q9.1 R8.2 U4.4 | length 32.2
  Top Layer w0.25: v1(57.25,21.9) 59.175,21.9 ; Q6.1@60.65,27.1 61.275,26.475 61.275,25.939 62.075,25.139 62.075,21.9 59.175,21.9 ; Q9.1@63.65,17.8 63.475,17.975 63.475,20.925 62.5,21.9 59.175,21.9
  Signal Layer 2 w0.305: v1@46.475,19.45 54.477,19.45 56.927,21.9 v1@56.975,21.9
  Bottom Layer w0.25: v1(46.55,19.5) 46.55,19.35 47.05,18.85 D11.2@47,18.8 ; v1(57.25,21.9) 57.425,21.725 U4.4@57.425,20.775
S: C4.1 C5.1 C6.1 C7.1 L3.1 L4.1
  other v6: 66.125,6.95
SGND: C1.1 C3.2 C4.2 C5.2 C6.2 C7.2 C8.2 C10.2 C15.2 C18.2 C20.2 C21.2 C27.1 C29.1 C31.2 C32.2 C33.1 C41.1 D3.2 D13.2 DE1.1 DE2.1 J2.A1 J2.A12 J2.B1 J2.B12 J2.M1 J2.M2 J2.S1 J2.S2 J2.S3 J2.S4 Q_SR1.1 Q_SR1.2 Q_SR1.3 R41.1 R96.2 U2.2 U6.4 U6.11 U6.17 U6.18 U6.25@73.62,33.845 U7.3 | length 56.9
  Top Layer w0.3: J2.B12@69.825,9.295 69.825,10.505 J2.A1@69.875,10.555 ; J2.A12@75.375,10.555 75.425,10.505 J2.B1@75.425,9.295
  Top Layer w0.4: C29.1@48.175,4.325 49.375,3.125 49.625,3.125
  Signal Layer 1 w1: 48.1,8.65 48.1,10.275 v7(49.875,12.05)
  Signal Layer 2 w0.4: C3.2@54.475,1.7 C3.2@54.475,2.125
  Signal Layer 2 w0.8: C3.2@54.575,2.125 55.425,2.975
  Bottom Layer w0.25: U6.11@74.37,35.745 74.37,34.595 v3(73.62,33.845) U6.25@74.645,32.82 ; U6.17@75.52,33.095 75.52,32.82 U6.18@75.52,32.595 75.67,32.445 ; C21.2@76.112,30.55 76.115,30.553 76.115,32 75.67,32.445 ; C15.2@76.945,32.445 75.67,32.445
  Bottom Layer w0.254: R41.1@68.9,25.475 68.9,25.712 69.6,26.412 U7.3@69.6,29.275 68.925,29.95 68.925,33.795 69.225,34.095 U6.4@71.72,34.095 73.37,34.095 v3(73.62,33.845) ; U7.3@69.7,29.475 C20.2@69.7,31.125
  Bottom Layer w0.3: C1.1@44.825,3.938 45.238,3.938 45.85,4.55 49.075,4.55 ; C41.1@46.575,2.15 C27.1@48.1,2.15 48.3,2.35 48.3,3.775 49.075,4.55 ; 51.15,5.1 50.6,4.55 ; 51.225,5.45 U2.2@50.325,4.55 ; 51.725,4.55 50.65,4.55 ; D3.2@73.65,15.825 74.375,16.55 74.375,17.65 C10.2@74.45,17.725 ; 49.075,4.55 U2.2@49.925,4.55 U2.2@50.325,4.55 ; U2.2@50.325,4.55 50.6,4.55 ; U2.2@50.325,4.55 51.075,3.8 v1(51.4,3.8) 50.65,4.55 ; 50.6,4.55 50.65,4.55
  Bottom Layer w0.35: 69.225,34.095 69.3,34.17 R96.2@69.3,34.875 C18.2@69.3,35.925
  Bottom Layer w0.6: Q_SR1.1@52.425,4.42 Q_SR1.2@52.425,5.69 Q_SR1.3@52.425,6.96 ; U6.25@74.645,32.82 75.52,32.82
  other v1: 59.65,0.925 60.475,0.925 64.271,0.933 65.096,0.933 65.896,0.933 52.194,1.155 52.949,1.155 53.719,1.155 59.675,1.675 60.5,1.675 64.271,1.683 65.096,1.683 65.896,1.683 52.95,1.975 51.394,1.98 52.169,1.98 53.719,1.98 51.4,2.975 52.125,2.975 52.15,3.8 74.575,15.95 74.575,16.575 74.575,17.2 76.475,21.425 76.275,30.4
  other v3: 73.62,32.745 72.52,33.845 74.72,33.845 73.62,34.945
  other v5: 51.175,1.1
  other v8: 58.6,1.55
SWS: C38.1 Dz1.1 R35.1 R36.1 U4.5 | length 10
  Top Layer w0.254: 56.344,22.943 57.475,24.075 57.475,24.499 57.95,24.975 57.95,26.125 58.188,26.363 R35.1@58.188,28.325 ; C38.1@57.537,24.2 57.6,24.137 C38.1@57.6,23.95 ; v1(58,22.575) 57.6,22.975 C38.1@57.6,23.95 ; R36.1@58.375,23.7 57.85,23.7 C38.1@57.6,23.95
  Bottom Layer w0.254: v1(58,22.575) 58.075,22.5 U4.5@58.075,21.425
VAS: D17.2 | length 1.6
  Top Layer w0.4: D17.2@48.583,10.033 50.058,10.033 v5(50.125,10.1)
VAUX: C15.1 U6.14 U6.15 U6.16 | length 2.2
  Bottom Layer w0.35: C15.1@76.895,33.595 C15.1@77.05,33.75
  Bottom Layer w0.6: 75.525,33.8 75.525,34.4 ; 75.55,33.775 C15.1@76.925,33.775
VBUS: C2.1 C10.1 D3.1 J2.A4 J2.A9 J2.B4 J2.B9 R1.2 R12.2 U6.21 | length 37.4
  Top Layer w0.25: J2.A4@71.375,10.555 71.375,9.345 J2.B9@71.425,9.295 ; J2.B4@73.825,9.295 73.875,9.345 J2.A9@73.875,10.555
  Signal Layer 1 w0.25: J2.B9@71.425,9.295 71.552,9.422 71.552,27.752 v1(72.175,28.375) 74.05,28.375 v1(74.25,28.175)
  Bottom Layer w0.25: R12.2@70.675,29.55 71,29.55 v1(72.175,28.375) ; J2.B9@71.425,9.295 71.425,9.475 71.925,9.975 73.145,9.975 73.225,9.895 73.274,9.895 73.825,9.344 J2.B4@73.825,9.295 ; U6.21@73.87,31.945 73.875,28.925 C2.1@73.875,28.85 ; C2.1@74.125,28.925 74.125,28.3 v1(74.25,28.175) ; C10.1@76.5,17.466 C10.1@76.566,17.4
  Bottom Layer w0.635: R1.2@75.7,13.525 76.566,14.391 C10.1@76.566,17.4
VCC: C61.1 R65.1 U10.3 | length 3
  Bottom Layer w0.35: R65.1@31.8,30.125 R65.1@31.875,30.125 ; U10.3@31.9,31.775 31.9,30.15 R65.1@31.875,30.125 ; C61.1@33.175,30.125 R65.1@31.875,30.125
